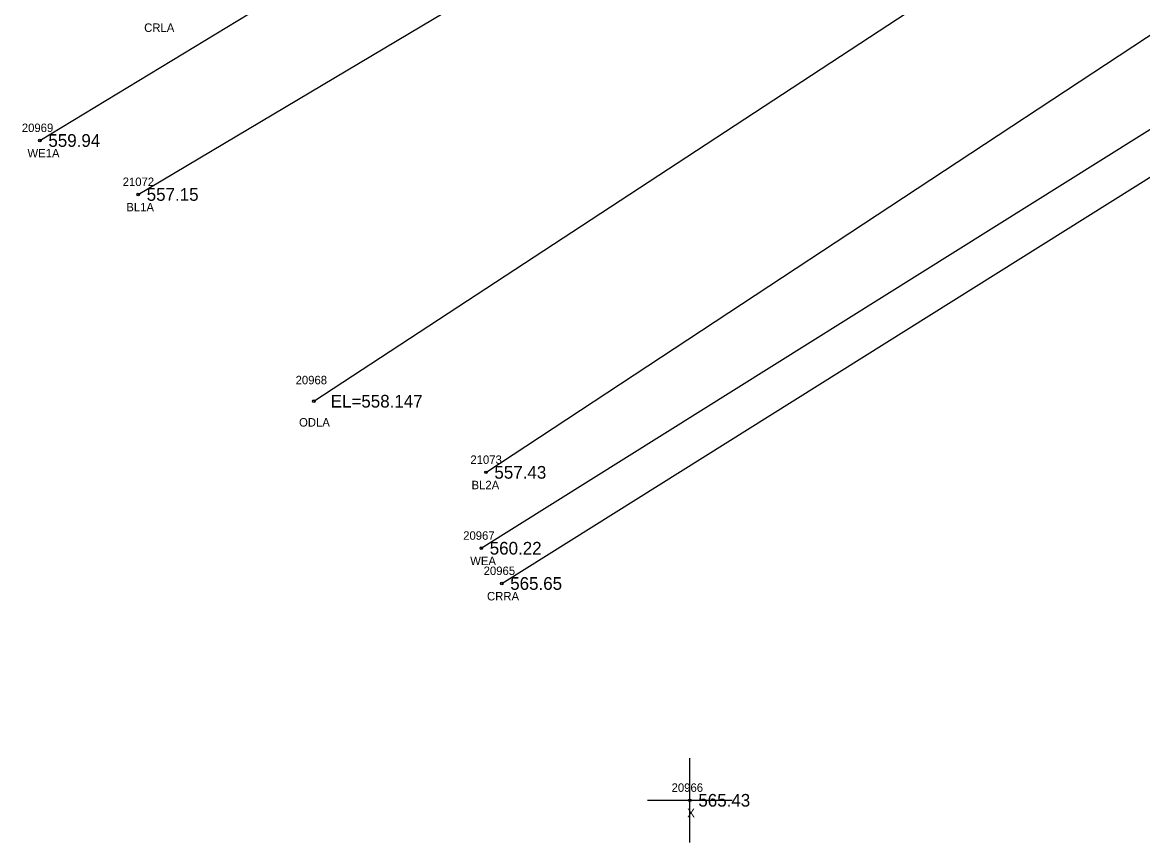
# Model space of a CAD drawing. Extents: x 1695443 to 1696344, y 1087542 to 1090645.
# Drawn here: x 1695464.2 to 1695596.7, y 1088673.4 to 1088770.4 of the extents above; entities that cross this region are included whole.
import ezdxf

# ---------------------------------------------------------------- set-up
doc = ezdxf.new("R2010")
doc.units = 0
for name, color, linetype in [('RD_DTM_BkLn1', 7, 'Continuous'), ('RD_DTM_BkLn_txCode', 7, 'Continuous'), ('RD_EX_H2O', 7, 'Continuous'), ('RD_EX_H2O_txCode', 7, 'Continuous'), ('RD_EX_Misc', 7, 'Continuous'), ('RD_EX_Misc_txCode', 7, 'Continuous'), ('RD_EX_TX_H2O_ELEV', 7, 'Continuous'), ('RD_EX_TX_Misc_ELEV', 7, 'Continuous'), ('RD_SMD_Locator', 7, 'Continuous')]:
    doc.layers.add(name, color=color, linetype=linetype)

msp = doc.modelspace()

# ---------------------------------------------------------------- linework, layer by layer
at = {"layer": 'RD_DTM_BkLn1'}
for points in [[(1695477.93, 1088750.04), (1695615.7, 1088831.98), (1695678.81, 1088884.02), (1695727.39, 1088931.9), (1695787.9, 1089007.61), (1695838.8, 1089064.32), (1695878.44, 1089095.49), (1695937, 1089135.88), (1696036.12, 1089170.43), (1696157.88, 1089137.18), (1696204, 1089102.76), (1696222.69, 1089094.08), (1696233.22, 1089076.04), (1696249.95, 1089031.73), (1696253.49, 1088951.92)], [(1695519.05, 1088717.19), (1695621.07, 1088784.34), (1695706.03, 1088842.06), (1695754.64, 1088904.72), (1695822.43, 1088986.95), (1695872.19, 1089035.65), (1695897.24, 1089064.09), (1695953.83, 1089097.9), (1696039.66, 1089119.12), (1696131.31, 1089103.56), (1696189.39, 1089073.13), (1696217.04, 1089023.97), (1696212.37, 1088964.66)]]:
    msp.add_lwpolyline(points, dxfattribs=at)
at = {"layer": 'RD_EX_H2O'}
for points in [[(1695466.3, 1088756.42), (1695582.06, 1088826.6), (1695651.04, 1088873.87), (1695702.34, 1088921.12), (1695742.91, 1088967.28), (1695775.02, 1089011.92), (1695840.03, 1089086.93), (1695863.99, 1089105.53), (1695935.01, 1089145.27), (1696036.06, 1089178.39), (1696162.35, 1089145.09), (1696220.48, 1089108.56), (1696243.56, 1089079.86), (1696260.75, 1089035.89), (1696273.81, 1089006.71), (1696286.66, 1088942.65)], [(1695498.69, 1088725.6), (1695608.54, 1088797.54), (1695668.72, 1088841.78), (1695723.76, 1088906.07), (1695797.15, 1088991.78), (1695861.15, 1089050.89), (1695886.72, 1089073.86), (1695948.49, 1089109.39), (1696039, 1089143.17), (1696151.62, 1089114.84), (1696213.01, 1089073.69), (1696220.87, 1089032.47), (1696230.14, 1088992.72), (1696246.9, 1088917.69)], [(1695518.5, 1088708.22), (1695626.45, 1088775.86), (1695695.79, 1088824.57), (1695753.51, 1088889.68), (1695821.81, 1088964.67), (1695880.24, 1089030.4), (1695903.5, 1089050.75), (1695958.92, 1089087.13), (1696042.79, 1089112.69), (1696142.64, 1089092.08), (1696193.08, 1089060.79), (1696207.36, 1089030.79), (1696205.38, 1088967.18), (1696218.5, 1088901.4)], [(1695520.92, 1088704.05), (1695627.53, 1088770.84), (1695697.51, 1088817.15), (1695757.08, 1088884.85), (1695828.4, 1088961.5), (1695887.69, 1089025.09), (1695910.13, 1089043.49), (1695963.83, 1089083.42), (1696041.69, 1089105.91), (1696137.07, 1089082.48), (1696174.24, 1089034.61), (1696185.76, 1089011.54), (1696200.45, 1088973.14), (1696214.06, 1088899.28)]]:
    msp.add_lwpolyline(points, dxfattribs=at)
at = {"layer": 'RD_EX_Misc'}
for p, q in [((1695543.17, 1088673.42), (1695543.17, 1088683.42)), ((1695538.17, 1088678.42), (1695548.17, 1088678.42))]:
    msp.add_line(p, q, dxfattribs=at)
at = {"layer": 'RD_SMD_Locator'}
for centre in [(1695466.3, 1088756.42), (1695477.93, 1088750.04), (1695498.69, 1088725.6), (1695519.05, 1088717.19), (1695518.5, 1088708.22), (1695520.92, 1088704.05), (1695543.17, 1088678.42)]:
    msp.add_circle(centre, 0.15, dxfattribs=at)

# ---------------------------------------------------------------- texts
at = {"layer": 'RD_DTM_BkLn_txCode'}
for s, p in [('21072', (1695476.09, 1088751.04)), ('BL1A', (1695476.52, 1088748.04)), ('21073', (1695517.21, 1088718.19)), ('BL2A', (1695517.35, 1088715.19))]:
    msp.add_text(s, height=1, dxfattribs=at).set_placement(p)
at = {"layer": 'RD_EX_H2O_txCode'}
for s, p in [('CRLA', (1695478.63, 1088769.26)), ('20969', (1695464.16, 1088757.42)), ('WE1A', (1695464.83, 1088754.42)), ('20968', (1695496.54, 1088727.6)), ('ODLA', (1695496.95, 1088722.6)), ('20967', (1695516.36, 1088709.22)), ('WEA', (1695517.19, 1088706.22)), ('20965', (1695518.78, 1088705.05)), ('CRRA', (1695519.18, 1088702.05))]:
    msp.add_text(s, height=1, dxfattribs=at).set_placement(p)
at = {"layer": 'RD_EX_Misc_txCode'}
for s, p in [('20966', (1695541.01, 1088679.42)), ('X', (1695542.86, 1088676.42))]:
    msp.add_text(s, height=1, dxfattribs=at).set_placement(p)
at = {"layer": 'RD_EX_TX_H2O_ELEV'}
for s, p in [('559.94', (1695467.3, 1088755.67)), ('EL=558.147', (1695500.69, 1088724.85)), ('560.22', (1695519.5, 1088707.47)), ('565.65', (1695521.92, 1088703.3))]:
    msp.add_text(s, height=1.5, dxfattribs=at).set_placement(p)
at = {"layer": 'RD_EX_TX_Misc_ELEV'}
for s, p in [('557.15', (1695478.93, 1088749.29)), ('557.43', (1695520.05, 1088716.44)), ('565.43', (1695544.17, 1088677.67))]:
    msp.add_text(s, height=1.5, dxfattribs=at).set_placement(p)

doc.saveas('drawing.dxf')
